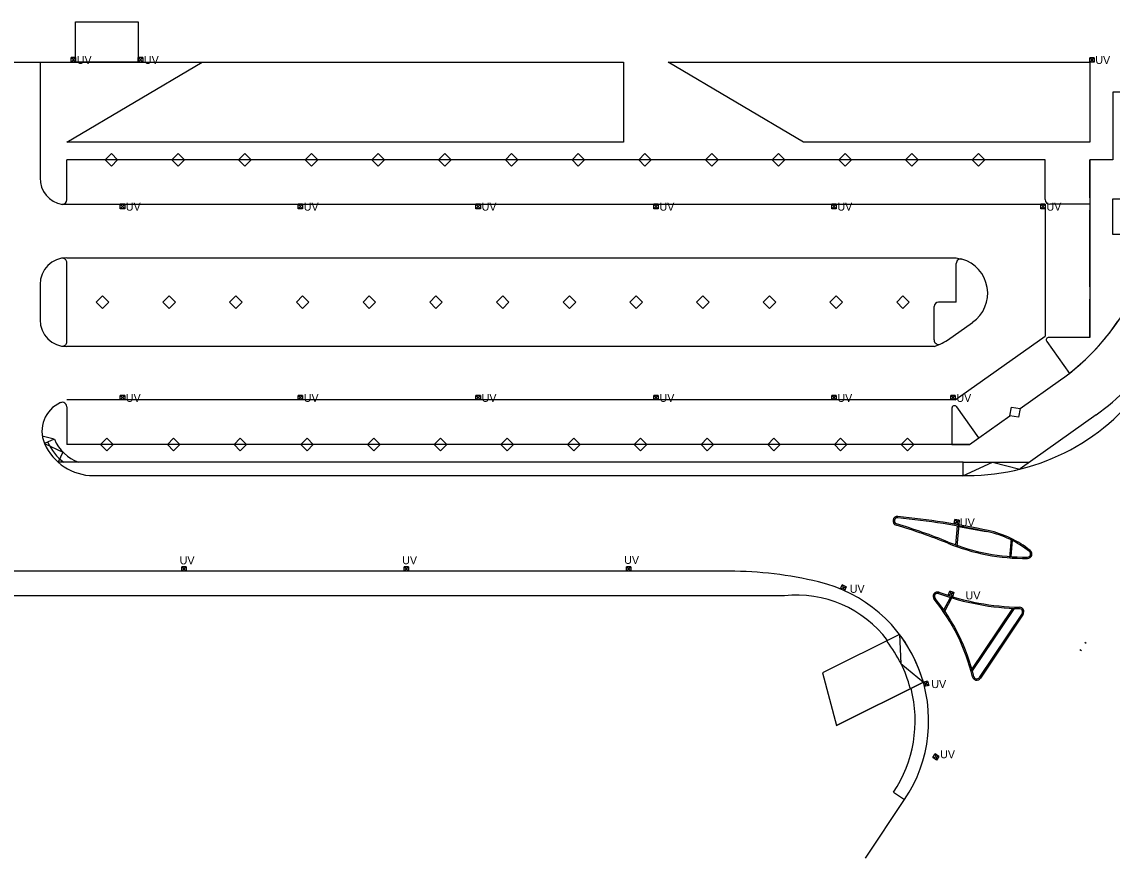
# Model space of a CAD drawing. Extents: x -264222 to -263676, y -1242344 to -1242060.
# Drawn here: x -263922.1 to -263799.5, y -1242344.5 to -1242250.5 of the extents above; entities that cross this region are included whole.
import ezdxf

# ---------------------------------------------------------------- set-up
doc = ezdxf.new("R2010")
doc.units = 0
doc.layers.add('PROJEKT_DRS_OBRUBNIKY_KOMUNIKACIE', color=7, linetype='Continuous')
doc.layers.add('PROJEKT_DRS_UV_STAVBY', color=7, linetype='Continuous')

msp = doc.modelspace()

# ---------------------------------------------------------------- linework, layer by layer
at = {"layer": 'PROJEKT_DRS_OBRUBNIKY_KOMUNIKACIE'}
for p, q in [((-263916.09, -1242254.98), (-263916.09, -1242250.46)), ((-263916.09, -1242250.46), (-263909.04, -1242250.46)), ((-263909.04, -1242250.46), (-263909.04, -1242254.98)), ((-263929.58, -1242254.98), (-263920.08, -1242254.98)), ((-263920.08, -1242254.98), (-263920.08, -1242267.98)), ((-263920.08, -1242254.98), (-263901.87, -1242254.98)), ((-263909.04, -1242254.98), (-263916.09, -1242254.98)), ((-263807.07, -1242265.99), (-263917.08, -1242265.98)), ((-263917.08, -1242270.48), (-263917.08, -1242265.98)), ((-263807.07, -1242270.45), (-263807.07, -1242265.99)), ((-263802.07, -1242270.24), (-263802.07, -1242265.99)), ((-263917.58, -1242270.98), (-263807.07, -1242270.98)), ((-263807.07, -1242270.98), (-263807.07, -1242285.82)), ((-263802.07, -1242270.95), (-263806.57, -1242270.95)), ((-263802.07, -1242280.24), (-263802.07, -1242271.65)), ((-263918.24, -1242277.22), (-263918.76, -1242277.49)), ((-263917.68, -1242277.04), (-263918.24, -1242277.22)), ((-263917.08, -1242276.98), (-263917.68, -1242277.04)), ((-263917.59, -1242277.03), (-263917.68, -1242277.04)), ((-263917.5, -1242277.04), (-263917.59, -1242277.03)), ((-263917.42, -1242277.06), (-263917.5, -1242277.04)), ((-263917.34, -1242277.1), (-263917.42, -1242277.06)), ((-263917.26, -1242277.15), (-263917.34, -1242277.1)), ((-263917.2, -1242277.21), (-263917.26, -1242277.15)), ((-263917.15, -1242277.28), (-263917.2, -1242277.21)), ((-263917.11, -1242277.36), (-263917.15, -1242277.28)), ((-263917.09, -1242277.44), (-263917.11, -1242277.36)), ((-263917.08, -1242276.98), (-263817.07, -1242276.98)), ((-263817.07, -1242276.98), (-263816.43, -1242277.14)), ((-263919.58, -1242278.32), (-263919.85, -1242278.84)), ((-263919.21, -1242277.87), (-263919.58, -1242278.32)), ((-263918.76, -1242277.49), (-263919.21, -1242277.87)), ((-263917.08, -1242277.53), (-263917.09, -1242277.44)), ((-263917.08, -1242286.43), (-263917.08, -1242277.53)), ((-263817.07, -1242281.98), (-263817.07, -1242277.62)), ((-263920.02, -1242279.4), (-263920.08, -1242279.98)), ((-263919.85, -1242278.84), (-263920.02, -1242279.4)), ((-263920.08, -1242279.98), (-263920.08, -1242283.98)), ((-263817.07, -1242281.98), (-263819.07, -1242281.98)), ((-263802.07, -1242285.95), (-263802.07, -1242281.65)), ((-263819.57, -1242286.23), (-263819.57, -1242282.48)), ((-263920.08, -1242283.98), (-263920.02, -1242284.57)), ((-263920.02, -1242284.57), (-263919.85, -1242285.13)), ((-263818.06, -1242286.25), (-263815.23, -1242284.25)), ((-263919.85, -1242285.13), (-263919.58, -1242285.64)), ((-263919.58, -1242285.64), (-263919.21, -1242286.1)), ((-263817.19, -1242292.98), (-263807.07, -1242285.82)), ((-263919.21, -1242286.1), (-263918.76, -1242286.47)), ((-263918.76, -1242286.47), (-263918.24, -1242286.75)), ((-263918.24, -1242286.75), (-263917.68, -1242286.92)), ((-263917.68, -1242286.92), (-263917.08, -1242286.98)), ((-263917.68, -1242286.92), (-263917.59, -1242286.93)), ((-263917.59, -1242286.93), (-263917.5, -1242286.93)), ((-263917.5, -1242286.93), (-263917.42, -1242286.9)), ((-263917.42, -1242286.9), (-263917.34, -1242286.87)), ((-263917.34, -1242286.87), (-263917.26, -1242286.82)), ((-263917.26, -1242286.82), (-263917.2, -1242286.76)), ((-263917.2, -1242286.76), (-263917.15, -1242286.69)), ((-263917.15, -1242286.69), (-263917.11, -1242286.61)), ((-263917.11, -1242286.61), (-263917.09, -1242286.52)), ((-263917.09, -1242286.52), (-263917.08, -1242286.43)), ((-263819.57, -1242286.98), (-263917.08, -1242286.98)), ((-263819.57, -1242286.98), (-263818.88, -1242286.7)), ((-263809.9, -1242293.95), (-263805.34, -1242290.73)), ((-263817.19, -1242292.98), (-263917.08, -1242292.98)), ((-263917.08, -1242293.74), (-263917.08, -1242297.98)), ((-263817.56, -1242293.87), (-263817.57, -1242293.93)), ((-263817.57, -1242293.93), (-263817.57, -1242297.98)), ((-263817.55, -1242293.81), (-263817.56, -1242293.87)), ((-263817.52, -1242293.76), (-263817.55, -1242293.81)), ((-263817.48, -1242293.72), (-263817.52, -1242293.76)), ((-263817.44, -1242293.68), (-263817.48, -1242293.72)), ((-263817.39, -1242293.65), (-263817.44, -1242293.68)), ((-263817.33, -1242293.63), (-263817.39, -1242293.65)), ((-263817.27, -1242293.63), (-263817.33, -1242293.63)), ((-263817.21, -1242293.63), (-263817.27, -1242293.63)), ((-263817.16, -1242293.65), (-263817.21, -1242293.63)), ((-263817.11, -1242293.67), (-263817.16, -1242293.65)), ((-263817.06, -1242293.71), (-263817.11, -1242293.67)), ((-263817.02, -1242293.75), (-263817.06, -1242293.71)), ((-263814.55, -1242297.24), (-263817.02, -1242293.75)), ((-263814.55, -1242297.24), (-263811.05, -1242294.76)), ((-263809.87, -1242300.67), (-263801.34, -1242294.63)), ((-263918.48, -1242297.4), (-263919.83, -1242297.03)), ((-263918.48, -1242297.4), (-263919.58, -1242297.88)), ((-263815.6, -1242297.98), (-263917.08, -1242297.98)), ((-263817.57, -1242297.98), (-263815.6, -1242297.98)), ((-263815.6, -1242297.98), (-263814.55, -1242297.24)), ((-263816.31, -1242299.98), (-263918.05, -1242299.98)), ((-263816.31, -1242301.48), (-263816.31, -1242299.98)), ((-263816.31, -1242299.98), (-263808.9, -1242299.98)), ((-263809.91, -1242300.76), (-263809.87, -1242300.67)), ((-263914.08, -1242301.48), (-263815.82, -1242301.48)), ((-263816.96, -1242307.13), (-263817.15, -1242309.26)), ((-263816.8, -1242307.01), (-263817.01, -1242309.47)), ((-263816.82, -1242307.21), (-263813.71, -1242307.77)), ((-263810.91, -1242308.55), (-263811.1, -1242310.72)), ((-263810.78, -1242308.78), (-263810.93, -1242310.58)), ((-263842.6, -1242312.24), (-263924.19, -1242312.23)), ((-264038.44, -1242314.98), (-263836.4, -1242314.98)), ((-263818.47, -1242316.58), (-263817.71, -1242315.18)), ((-263818.45, -1242316.87), (-263817.49, -1242315.09)), ((-263810.75, -1242316.41), (-263815.43, -1242323.41)), ((-263810.58, -1242316.41), (-263815.27, -1242323.44)), ((-263809.68, -1242316.98), (-263814.48, -1242324.17)), ((-263809.55, -1242317.06), (-263814.36, -1242324.25)), ((-263823.44, -1242319.35), (-263832.11, -1242323.65)), ((-263802.61, -1242320.22), (-263802.45, -1242320.33)), ((-263813.54, -1242320.69), (-263813.54, -1242320.69)), ((-263803.16, -1242321.04), (-263802.99, -1242321.15)), ((-263832.11, -1242323.65), (-263830.54, -1242329.57)), ((-263820.77, -1242324.72), (-263830.54, -1242329.57)), ((-263824.13, -1242337.08), (-263822.88, -1242337.91)), ((-263827.28, -1242344.5), (-263822.88, -1242337.91))]:
    msp.add_line(p, q, dxfattribs=at)
for points in [[(-263854.47, -1242263.98), (-263917.08, -1242263.98), (-263901.87, -1242254.98), (-263854.47, -1242254.98), (-263854.47, -1242263.98)], [(-263802.07, -1242263.99), (-263834.26, -1242263.98), (-263849.47, -1242254.98), (-263802.07, -1242254.99), (-263802.07, -1242263.99)], [(-263798.06, -1242282.88), (-263794.99, -1242278.38), (-263796.97, -1242278.38), (-263796.97, -1242274.38), (-263799.47, -1242274.38), (-263799.47, -1242270.38), (-263791.97, -1242270.38), (-263791.97, -1242266.38), (-263796.97, -1242266.38), (-263796.97, -1242260.38), (-263791.97, -1242260.38), (-263791.97, -1242258.38), (-263799.47, -1242258.38), (-263799.47, -1242265.99), (-263802.07, -1242265.99)], [(-263912.07, -1242265.28), (-263911.36, -1242265.99), (-263912.07, -1242266.69), (-263912.77, -1242265.99), (-263912.07, -1242265.28)], [(-263904.57, -1242265.28), (-263903.86, -1242265.99), (-263904.57, -1242266.69), (-263905.27, -1242265.99), (-263904.57, -1242265.28)], [(-263897.07, -1242265.28), (-263896.36, -1242265.99), (-263897.07, -1242266.69), (-263897.77, -1242265.99), (-263897.07, -1242265.28)], [(-263897.07, -1242265.28), (-263896.36, -1242265.99), (-263897.07, -1242266.69), (-263897.77, -1242265.99), (-263897.07, -1242265.28)], [(-263889.57, -1242265.28), (-263888.86, -1242265.99), (-263889.57, -1242266.69), (-263890.27, -1242265.99), (-263889.57, -1242265.28)], [(-263882.07, -1242265.28), (-263881.36, -1242265.99), (-263882.07, -1242266.69), (-263882.77, -1242265.99), (-263882.07, -1242265.28)], [(-263874.57, -1242265.28), (-263873.86, -1242265.99), (-263874.57, -1242266.69), (-263875.27, -1242265.99), (-263874.57, -1242265.28)], [(-263867.07, -1242265.28), (-263866.36, -1242265.99), (-263867.07, -1242266.69), (-263867.77, -1242265.99), (-263867.07, -1242265.28)], [(-263859.57, -1242265.28), (-263858.86, -1242265.99), (-263859.57, -1242266.69), (-263860.27, -1242265.99), (-263859.57, -1242265.28)], [(-263852.07, -1242265.28), (-263851.36, -1242265.99), (-263852.07, -1242266.69), (-263852.77, -1242265.99), (-263852.07, -1242265.28)], [(-263844.57, -1242265.28), (-263843.86, -1242265.99), (-263844.57, -1242266.69), (-263845.27, -1242265.99), (-263844.57, -1242265.28)], [(-263837.07, -1242265.28), (-263836.36, -1242265.99), (-263837.07, -1242266.69), (-263837.77, -1242265.99), (-263837.07, -1242265.28)], [(-263829.57, -1242265.28), (-263828.86, -1242265.99), (-263829.57, -1242266.69), (-263830.27, -1242265.99), (-263829.57, -1242265.28)], [(-263822.07, -1242265.28), (-263821.36, -1242265.99), (-263822.07, -1242266.69), (-263822.77, -1242265.99), (-263822.07, -1242265.28)], [(-263814.57, -1242265.28), (-263813.86, -1242265.99), (-263814.57, -1242266.69), (-263815.27, -1242265.99), (-263814.57, -1242265.28)], [(-263802.07, -1242265.99), (-263802.07, -1242270.24), (-263802.07, -1242270.95), (-263802.07, -1242271.65), (-263802.07, -1242273.45), (-263802.07, -1242275.95), (-263802.07, -1242278.45), (-263802.07, -1242280.24), (-263802.07, -1242281.65), (-263802.07, -1242283.45), (-263802.07, -1242285.95), (-263806.66, -1242285.94)], [(-263913.07, -1242281.28), (-263912.36, -1242281.98), (-263913.07, -1242282.69), (-263913.77, -1242281.98), (-263913.07, -1242281.28)], [(-263905.57, -1242281.28), (-263904.86, -1242281.98), (-263905.57, -1242282.69), (-263906.27, -1242281.98), (-263905.57, -1242281.28)], [(-263898.07, -1242281.28), (-263897.36, -1242281.98), (-263898.07, -1242282.69), (-263898.77, -1242281.98), (-263898.07, -1242281.28)], [(-263890.57, -1242281.28), (-263889.86, -1242281.98), (-263890.57, -1242282.69), (-263891.27, -1242281.98), (-263890.57, -1242281.28)], [(-263890.57, -1242281.28), (-263889.86, -1242281.98), (-263890.57, -1242282.69), (-263891.27, -1242281.98), (-263890.57, -1242281.28)], [(-263883.07, -1242281.28), (-263882.36, -1242281.98), (-263883.07, -1242282.69), (-263883.77, -1242281.98), (-263883.07, -1242281.28)], [(-263875.57, -1242281.28), (-263874.86, -1242281.98), (-263875.57, -1242282.69), (-263876.27, -1242281.98), (-263875.57, -1242281.28)], [(-263868.07, -1242281.28), (-263867.36, -1242281.98), (-263868.07, -1242282.69), (-263868.77, -1242281.98), (-263868.07, -1242281.28)], [(-263860.57, -1242281.28), (-263859.86, -1242281.98), (-263860.57, -1242282.69), (-263861.27, -1242281.98), (-263860.57, -1242281.28)], [(-263853.07, -1242281.28), (-263852.36, -1242281.98), (-263853.07, -1242282.69), (-263853.77, -1242281.98), (-263853.07, -1242281.28)], [(-263845.57, -1242281.28), (-263844.86, -1242281.98), (-263845.57, -1242282.69), (-263846.27, -1242281.98), (-263845.57, -1242281.28)], [(-263838.07, -1242281.28), (-263837.36, -1242281.98), (-263838.07, -1242282.69), (-263838.77, -1242281.98), (-263838.07, -1242281.28)], [(-263830.57, -1242281.28), (-263829.86, -1242281.98), (-263830.57, -1242282.69), (-263831.27, -1242281.98), (-263830.57, -1242281.28)], [(-263823.07, -1242281.28), (-263822.36, -1242281.98), (-263823.07, -1242282.69), (-263823.77, -1242281.98), (-263823.07, -1242281.28)], [(-263806.9, -1242286.42), (-263804.35, -1242290.02), (-263802.55, -1242288.44)], [(-263810.88, -1242293.78), (-263809.9, -1242293.95), (-263810.06, -1242294.93), (-263811.05, -1242294.76), (-263810.88, -1242293.78)], [(-263919.58, -1242297.88), (-263917.52, -1242298.83), (-263918.05, -1242299.98)], [(-263912.57, -1242297.28), (-263911.86, -1242297.98), (-263912.57, -1242298.69), (-263913.27, -1242297.98), (-263912.57, -1242297.28)], [(-263905.07, -1242297.28), (-263904.36, -1242297.98), (-263905.07, -1242298.69), (-263905.77, -1242297.98), (-263905.07, -1242297.28)], [(-263897.57, -1242297.28), (-263896.86, -1242297.98), (-263897.57, -1242298.69), (-263898.27, -1242297.98), (-263897.57, -1242297.28)], [(-263890.07, -1242297.28), (-263889.36, -1242297.98), (-263890.07, -1242298.69), (-263890.77, -1242297.98), (-263890.07, -1242297.28)], [(-263890.07, -1242297.28), (-263889.36, -1242297.98), (-263890.07, -1242298.69), (-263890.77, -1242297.98), (-263890.07, -1242297.28)], [(-263882.57, -1242297.28), (-263881.86, -1242297.98), (-263882.57, -1242298.69), (-263883.27, -1242297.98), (-263882.57, -1242297.28)], [(-263875.07, -1242297.28), (-263874.36, -1242297.98), (-263875.07, -1242298.69), (-263875.77, -1242297.98), (-263875.07, -1242297.28)], [(-263867.57, -1242297.28), (-263866.86, -1242297.98), (-263867.57, -1242298.69), (-263868.27, -1242297.98), (-263867.57, -1242297.28)], [(-263860.07, -1242297.28), (-263859.36, -1242297.98), (-263860.07, -1242298.69), (-263860.77, -1242297.98), (-263860.07, -1242297.28)], [(-263852.57, -1242297.28), (-263851.86, -1242297.98), (-263852.57, -1242298.69), (-263853.27, -1242297.98), (-263852.57, -1242297.28)], [(-263845.07, -1242297.28), (-263844.36, -1242297.98), (-263845.07, -1242298.69), (-263845.77, -1242297.98), (-263845.07, -1242297.28)], [(-263837.57, -1242297.28), (-263836.86, -1242297.98), (-263837.57, -1242298.69), (-263838.27, -1242297.98), (-263837.57, -1242297.28)], [(-263830.07, -1242297.28), (-263829.36, -1242297.98), (-263830.07, -1242298.69), (-263830.77, -1242297.98), (-263830.07, -1242297.28)], [(-263822.57, -1242297.28), (-263821.86, -1242297.98), (-263822.57, -1242298.69), (-263823.27, -1242297.98), (-263822.57, -1242297.28)], [(-263816.33, -1242301.51), (-263813, -1242299.98), (-263809.91, -1242300.76)], [(-263832.11, -1242323.65), (-263830.54, -1242329.57), (-263820.77, -1242324.72), (-263821.24, -1242323.31), (-263821.84, -1242321.94), (-263822.87, -1242320.15), (-263823.44, -1242319.35), (-263832.11, -1242323.65)], [(-263823.44, -1242319.35), (-263823.29, -1242322.62), (-263820.77, -1242324.72)]]:
    msp.add_lwpolyline(points, dxfattribs=at)
for centre, radius, start, end in [((-263917.12, -1242268.06), 2.96, 178.5315, 261.1367), ((-263917.58, -1242270.48), 0.5, 270.2865, 0), ((-263806.57, -1242270.45), 0.5, 180, 270), ((-263816.57, -1242277.62), 0.5, 73.8446, 180), ((-263817.54, -1242280.98), 4, 305.2702, 73.8446), ((-263819.07, -1242282.48), 0.5, 90, 180), ((-263821.81, -1242268.3), 27.86, 313.7192, 328.4502), ((-263820.07, -1242269.91), 25.5, 305.2702, 326.1165), ((-263806.66, -1242286.24), 0.3, 89.9436, 215.2702), ((-263819.07, -1242286.23), 0.5, 180, 291.8332), ((-263820.37, -1242282.98), 4, 291.8332, 305.2702), ((-263816.07, -1242273.82), 25.5, 305.2702, 326.1165), ((-263815.82, -1242276.98), 24.5, 270, 326.3992), ((-263916.37, -1242296.48), 3.5, 113.7599, 203.5782), ((-263917.58, -1242293.74), 0.5, 0, 113.7599), ((-263914.08, -1242295.48), 6, 203.5782, 270), ((-263914.08, -1242295.48), 5.6, 203.5782, 233.4725), ((-263914.08, -1242295.48), 4.8, 203.5782, 249.6359), ((-263823.69, -1242306.57), 0.5, 84.5031, 253.3726), ((-263823.69, -1242306.57), 0.35, 84.5031, 253.3726), ((-263832, -1242392.97), 87.14, 77.7452, 84.5031), ((-263832, -1242392.97), 87.29, 77.7452, 84.5031), ((-263842.68, -1242370.17), 65.87, 68.0197, 73.3726), ((-263842.68, -1242370.17), 66.02, 68.0197, 73.3726), ((-263815.91, -1242318.9), 11.35, 51.4912, 77.7452), ((-263815.91, -1242318.9), 11.5, 51.4912, 77.7452), ((-263809.23, -1242287.3), 23.5, 248.0197, 270.4085), ((-263809.23, -1242287.3), 23.35, 248.0197, 270.4085), ((-263809.06, -1242310.29), 0.5, 270.4085, 51.4912), ((-263809.06, -1242310.29), 0.35, 270.4085, 51.4912), ((-263842.43, -1242353.35), 41.11, 76.1362, 90.2415), ((-263836.18, -1242329.03), 16, 326.2529, 76.9695), ((-263835.04, -1242327.71), 12.8, 36.9205, 96.0874), ((-263819.18, -1242315.07), 0.5, 70.2828, 219.3857), ((-263836.18, -1242329.03), 21.5, 13.267, 39.3857), ((-263819.18, -1242315.07), 0.35, 70.2828, 219.3857), ((-263836.18, -1242329.03), 21.65, 13.267, 39.3857), ((-263809.23, -1242287.3), 29.15, 250.2828, 268.5641), ((-263809.23, -1242287.3), 29, 250.2828, 268.5641), ((-263809.97, -1242316.79), 0.35, 326.2529, 88.5641), ((-263809.97, -1242316.79), 0.5, 326.2529, 88.5641), ((-263836.18, -1242329.03), 14.4, 14.7256, 38.1157), ((-263836.18, -1242329.03), 21.65, 13.267, 14.9596), ((-263814.77, -1242323.98), 0.5, 193.267, 326.2529), ((-263814.77, -1242323.98), 0.35, 193.267, 326.2529), ((-263836.23, -1242329.02), 14.54, 326.3344, 14.4166)]:
    msp.add_arc(centre, radius, start, end, dxfattribs=at)
at = {"layer": 'PROJEKT_DRS_UV_STAVBY'}
for points in [[(-263916.59, -1242254.98), (-263916.59, -1242254.48), (-263916.09, -1242254.48), (-263916.09, -1242254.98), (-263916.59, -1242254.98), (-263916.09, -1242254.48), (-263916.59, -1242254.48), (-263916.09, -1242254.98)], [(-263909.04, -1242254.98), (-263909.04, -1242254.48), (-263908.54, -1242254.48), (-263908.54, -1242254.98), (-263909.04, -1242254.98), (-263908.54, -1242254.48), (-263909.04, -1242254.48), (-263908.54, -1242254.98)], [(-263802.07, -1242254.99), (-263802.07, -1242254.49), (-263801.57, -1242254.49), (-263801.57, -1242254.99), (-263802.07, -1242254.99), (-263801.57, -1242254.49), (-263802.07, -1242254.49), (-263801.57, -1242254.99)], [(-263911.07, -1242271.48), (-263911.07, -1242270.98), (-263910.57, -1242270.98), (-263910.57, -1242271.48), (-263911.07, -1242271.48), (-263910.57, -1242270.98), (-263911.07, -1242270.98), (-263910.57, -1242271.48)], [(-263891.07, -1242271.48), (-263891.07, -1242270.98), (-263890.57, -1242270.98), (-263890.57, -1242271.48), (-263891.07, -1242271.48), (-263890.57, -1242270.98), (-263891.07, -1242270.98), (-263890.57, -1242271.48)], [(-263871.07, -1242271.48), (-263871.07, -1242270.98), (-263870.57, -1242270.98), (-263870.57, -1242271.48), (-263871.07, -1242271.48), (-263870.57, -1242270.98), (-263871.07, -1242270.98), (-263870.57, -1242271.48)], [(-263851.07, -1242271.48), (-263851.07, -1242270.98), (-263850.57, -1242270.98), (-263850.57, -1242271.48), (-263851.07, -1242271.48), (-263850.57, -1242270.98), (-263851.07, -1242270.98), (-263850.57, -1242271.48)], [(-263831.07, -1242271.48), (-263831.07, -1242270.98), (-263830.57, -1242270.98), (-263830.57, -1242271.48), (-263831.07, -1242271.48), (-263830.57, -1242270.98), (-263831.07, -1242270.98), (-263830.57, -1242271.48)], [(-263807.57, -1242271.48), (-263807.57, -1242270.98), (-263807.07, -1242270.98), (-263807.07, -1242271.48), (-263807.57, -1242271.48), (-263807.07, -1242270.98), (-263807.57, -1242270.98), (-263807.07, -1242271.48)], [(-263911.07, -1242292.98), (-263911.07, -1242292.48), (-263910.57, -1242292.48), (-263910.57, -1242292.98), (-263911.07, -1242292.98), (-263910.57, -1242292.48), (-263911.07, -1242292.48), (-263910.57, -1242292.98)], [(-263891.07, -1242292.98), (-263891.07, -1242292.48), (-263890.57, -1242292.48), (-263890.57, -1242292.98), (-263891.07, -1242292.98), (-263890.57, -1242292.48), (-263891.07, -1242292.48), (-263890.57, -1242292.98)], [(-263871.07, -1242292.98), (-263871.07, -1242292.48), (-263870.57, -1242292.48), (-263870.57, -1242292.98), (-263871.07, -1242292.98), (-263870.57, -1242292.48), (-263871.07, -1242292.48), (-263870.57, -1242292.98)], [(-263851.07, -1242292.98), (-263851.07, -1242292.48), (-263850.57, -1242292.48), (-263850.57, -1242292.98), (-263851.07, -1242292.98), (-263850.57, -1242292.48), (-263851.07, -1242292.48), (-263850.57, -1242292.98)], [(-263831.07, -1242292.98), (-263831.07, -1242292.48), (-263830.57, -1242292.48), (-263830.57, -1242292.98), (-263831.07, -1242292.98), (-263830.57, -1242292.48), (-263831.07, -1242292.48), (-263830.57, -1242292.98)], [(-263817.69, -1242292.98), (-263817.69, -1242292.48), (-263817.19, -1242292.48), (-263817.19, -1242292.98), (-263817.69, -1242292.98), (-263817.19, -1242292.48), (-263817.69, -1242292.48), (-263817.19, -1242292.98)], [(-263817.3, -1242306.91), (-263817.22, -1242306.42), (-263816.73, -1242306.5), (-263816.8, -1242306.99), (-263817.3, -1242306.91), (-263816.73, -1242306.5), (-263817.22, -1242306.42), (-263816.8, -1242306.99)], [(-263904.16, -1242312.23), (-263904.16, -1242311.73), (-263903.66, -1242311.73), (-263903.66, -1242312.23), (-263904.16, -1242312.23), (-263903.66, -1242311.73), (-263904.16, -1242311.73), (-263903.66, -1242312.23)], [(-263879.16, -1242312.23), (-263879.16, -1242311.73), (-263878.66, -1242311.73), (-263878.66, -1242312.23), (-263879.16, -1242312.23), (-263878.66, -1242311.73), (-263879.16, -1242311.73), (-263878.66, -1242312.23)], [(-263854.16, -1242312.24), (-263854.16, -1242311.74), (-263853.66, -1242311.74), (-263853.66, -1242312.24), (-263854.16, -1242312.24), (-263853.66, -1242311.74), (-263854.16, -1242311.74), (-263853.66, -1242312.24)], [(-263830.1, -1242314.22), (-263829.9, -1242313.76), (-263829.44, -1242313.97), (-263829.64, -1242314.42), (-263830.1, -1242314.22), (-263829.44, -1242313.97), (-263829.9, -1242313.76), (-263829.64, -1242314.42)], [(-263817.97, -1242314.94), (-263817.81, -1242314.47), (-263817.33, -1242314.62), (-263817.49, -1242315.1), (-263817.97, -1242314.94), (-263817.33, -1242314.62), (-263817.81, -1242314.47), (-263817.49, -1242315.1)], [(-263820.64, -1242325.2), (-263820.77, -1242324.72), (-263820.29, -1242324.59), (-263820.16, -1242325.07), (-263820.64, -1242325.2), (-263820.29, -1242324.59), (-263820.77, -1242324.72), (-263820.16, -1242325.07)], [(-263819.72, -1242333.19), (-263819.44, -1242332.77), (-263819.03, -1242333.05), (-263819.31, -1242333.47), (-263819.72, -1242333.19), (-263819.03, -1242333.05), (-263819.44, -1242332.77), (-263819.31, -1242333.47)]]:
    msp.add_lwpolyline(points, dxfattribs=at)

# ---------------------------------------------------------------- texts
for p in [(-263915.96, -1242255.19), (-263908.41, -1242255.19), (-263801.44, -1242255.2), (-263910.44, -1242271.69), (-263890.44, -1242271.69), (-263870.44, -1242271.69), (-263850.44, -1242271.69), (-263830.44, -1242271.69), (-263806.93, -1242271.69), (-263910.44, -1242293.19), (-263890.44, -1242293.19), (-263870.44, -1242293.19), (-263850.44, -1242293.19), (-263830.44, -1242293.19), (-263817.06, -1242293.19), (-263816.67, -1242307.2), (-263904.39, -1242311.46), (-263879.37, -1242311.44), (-263854.41, -1242311.41), (-263829.05, -1242314.66), (-263816.03, -1242315.4), (-263819.88, -1242325.37), (-263818.89, -1242333.26)]:
    msp.add_text('UV', height=0.9, rotation=359.8587, dxfattribs=at).set_placement(p)

doc.saveas('drawing.dxf')
